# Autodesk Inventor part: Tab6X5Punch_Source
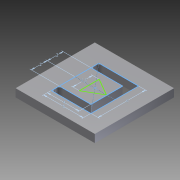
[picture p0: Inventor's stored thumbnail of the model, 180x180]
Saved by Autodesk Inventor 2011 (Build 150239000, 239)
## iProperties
Created: 2007-02
Part Number: Tab6X5Punch_Source
Material: Default
Document SubType Name: Sheet Metal
Designer: Autodesk, Inc.
Mass: 0.0862145 g
Surface Area: 2.41571 cm^2
Volume: 0.0862145 cm^3
Density: 1 g/cm^3
Sheet Metal Rule: 1 mm
Author: Autodesk, Inc.
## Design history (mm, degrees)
node "Face1"
  sketch "Sketch1"
    geometry: L1 (-5, 5)-(5, 5); L2 (5, 5)-(5, -5); L3 (5, -5)-(-5, -5); L4 (-5, -5)-(-5, 5); L5 (-5, 5)-(5, -5); 2 further points
    constraints: 10 end point, 2 parallel, 1 coincident, 1 horizontal, 1 midpoint, 1 perpendicular
    dimensions: "d0" = 10 distance of L1.start L1.end; "d1" = 10 distance of L1.end L2.end (= d0)
sketch "Sketch2"
  geometry: L1 (1.5, 2)-(1.5, -2); L2 (2.5, 3)-(2.5, -3); L3 (-2, 2)-(1.5, 2); L4 (-2, 3)-(2.5, 3); L5 (-2.5, 2.5)-(-2.5, 2.5); L6 (2.5, -3)-(-2, -3); L7 (1.5, -2)-(-2, -2); L8 (-2.5, -2.5)-(-2.5, -2.5); A1 r 0.5 centre (-2, 2.5) between (-2.5, 2.5) and (-2, 2); A2 r 0.5 centre (-2, 2.5) between (-2, 3) and (-2.5, 2.5); A3 r 0.5 centre (-2, -2.5) between (-2, -2) and (-2.5, -2.5); A4 r 0.5 centre (-2, -2.5) between (-2.5, -2.5) and (-2, -3); 3 further points
  constraints: 16 end point, 8 point on circle, 8 tangent, 4 centre point, 4 parallel, 3 equal radius, 2 horizontal, 2 perpendicular, 2 point on line, 1 coincident, 1 collinear
  dimensions: "d3" = 5 distance of point (-2.5, 3) L2.start; "d4" = 6 distance of L2.start L2.end; "d5" = 1 distance between parallel lines of L4 L3; "d6" = 1 distance between parallel lines of L6 L7 (= d5); "d7" = 1 distance between parallel lines of L2 L1; "d8" = 0.5 radius of A2; "d9" = 2.5 distance from line of point (0, 0) L2 (= 0.5 x d3); "d10" = 3 distance from line of point (0, 0) L6 (= 0.5 x d4)
cut "Cut1" sketch "Sketch2" dims "d11" = 1 (= Thickness), "d12" = 0
sketch "Sketch3"
  geometry: L1 (-2.5, 3)-(2.5, 3); L2 (2.5, 3)-(2.5, -3); L3 (2.5, -3)-(-2.5, -3); L4 (-2.5, -3)-(-2.5, 3); L5 (2.5, -3)-(-2.5, 3); L6 (1.443, 0)-(-0.722, -1.25); L7 (-0.722, -1.25)-(-0.722, 1.25); L8 (-0.722, 1.25)-(1.443, 0); L9 (-2.5, 0)-(2.5, 0); L10 (-2.5, 2)-(1.5, 2); L11 (1.5, 2)-(1.5, -2); L12 (1.5, -2)-(-2.5, -2); 4 further points
  constraints: 24 end point, 3 coincident, 3 midpoint, 3 parallel, 3 perpendicular, 2 point on line, 1 horizontal, 7 other
  dimensions: "d13" = 6 distance of L1.end L2.end; "d14" = 5 distance of L2.end L3.end; "d15" = 2.5 distance of L6.end L7.end; "d16" = 2 distance from line of L10 L9.start; "d17" = 2 distance from line of L9.start L12; "d18" = 4 distance between parallel lines of L11 L4
body "Solid1"
face "Plate1" dims "Thickness" = 1
other parameters: "BendRadius" = 0.5, "BendReliefWidth" = 1 (= Thickness), "BendReliefDepth" = 0.5 (= 0.5 x Thickness), "CornerReliefSize" = 4 (= 4 x Thickness), "SeamGap" = 0.01, "MinimumRemnant" = 2 (= 2 x Thickness), "TransitionRadius" = 0.5 (= BendRadius), "JacobiRadiusSize" = 1 (= Thickness), "d2" = 0.5 (= BendRadius), "GapSize" = 1 (= Thickness)
